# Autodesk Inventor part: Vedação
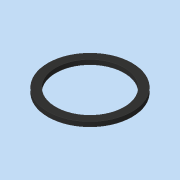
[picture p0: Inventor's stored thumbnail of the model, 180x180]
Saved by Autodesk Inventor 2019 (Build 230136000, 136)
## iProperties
Created: 2019-08
Part Number: Vedação
Material: Borracha
Document SubType Name: Modeling
Designer: Usuario
Density: 0.93 g/cm^3
Appearance: Borracha - Preta
Author: Usuario
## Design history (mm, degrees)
sketch "Esboço1"
  geometry: C1 r 9.35 at (0, 0); C2 r 11.5 at (0, 0); 1 further point
  constraints: 2 centre point, 2 coincident
  dimensions: "d0" = 18.7 diameter of C1; "d1" = 23 diameter of C2
extrude "Extrusão1" new body sketch "Esboço1" distance "d2" = 1.25; taper "d3" = 0 deg
node "Sólido1"
